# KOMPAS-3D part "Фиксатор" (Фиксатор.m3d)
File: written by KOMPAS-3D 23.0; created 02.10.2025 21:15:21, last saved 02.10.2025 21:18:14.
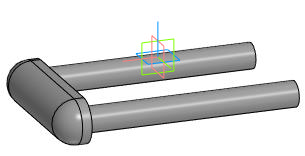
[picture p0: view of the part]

Document properties: Автор: Inspektor_Kot; Полное имя файла: I:\Autodesk Inventor Projects\ИМ-ИТ ЦД\Вариант 9\Фиксатор.m3d

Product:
- Part/product: Фиксатор
    Масса: 11.880354

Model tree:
1. Эскиз:1  (with: Элемент выдавливания:1, Элемент выдавливания:3)
2. Элемент выдавливания:1
     Расстояние 2 = 330
3. Эскиз:2  (with: Элемент выдавливания:1)
4. Элемент выдавливания:2
     Расстояние 1 = 50
5. Скругление:1  (with: Элемент выдавливания:2)
     Радиус = 35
